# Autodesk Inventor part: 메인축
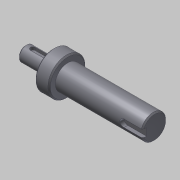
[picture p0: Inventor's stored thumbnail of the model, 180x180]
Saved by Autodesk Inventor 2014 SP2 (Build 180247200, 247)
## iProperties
Created: 2018-09
Part Number: 메인축
Document SubType Name: Modeling
Density: 7.86 g/cm^3
Material: 강철, 연강
Appearance: 강철
Mass: 251.949 g
Surface Area: 77.4412 cm^2
Volume: 32.0546 cm^3
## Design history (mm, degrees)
sketch "스케치1"
  geometry: L1 (34.997, -37.5)-(34.997, -77.5) reference; L2 (46.5, -38.401)-(46.5, -76.599) reference; L3 (12.497, -57.5)-(116.5, -57.5); L4 (12.497, -63.5)-(34.997, -63.5); L5 (34.997, -72.5)-(46.5, -72.5); L6 (46.5, -67.5)-(116.5, -67.5); L7 (116.5, -67.5)-(116.5, -57.5); L8 (12.497, -63.5)-(12.497, -57.5); 2 further points
  constraints: 12 end point, 5 point on line, 4 perpendicular, 1 midpoint, 1 parallel
  dimensions: "d0" = 20 diameter of L6 L3; "d1" = 30 diameter of L5 L3; "d2" = 22.5 distance of L4.start L4.end; "d3" = 70 distance of L6.start L6.end; "d5" = 12 diameter of L4 L3
revolve "회전1" sketch "스케치1" stored, may be unused: angle "d4" = 90 deg
chamfer "모따기1" distance "d6" = 1; stored, may be unused: second distance "d7" = 2, angle "d8" = 45 deg
node "작업 평면1"
sketch "스케치2"
  geometry: L1 (-11.25, -5)-(-11.25, 5) reference; L2 (-5.25, 2)-(4.75, 2); L3 (4.75, -2)-(-5.25, -2); A1 r 2 centre (4.75, 0) between (4.75, -2) and (4.75, 2); A2 r 2 centre (-5.25, 0) between (-5.25, 2) and (-5.25, -2); 2 further points
  constraints: 4 end point, 4 point on circle, 4 tangent, 2 centre point, 1 horizontal alignment, 1 midpoint, 1 parallel, 1 perpendicular
  dimensions: "d9" = 4 distance between parallel lines of L3 L2; "d10" = 14 dimension on A1 A2; "d11" = 4 distance edge to line of A2 L1
extrude "돌출1" cut sketch "스케치2" distance "d12" = 2.5; taper "d13" = 0 deg
node "작업 평면2"
sketch "스케치3"
  geometry: L1 (35, 9)-(35, -9) reference; L2 (35, 3)-(20, 3); L3 (20, -3)-(35, -3); A1 r 3 centre (20, 0) between (20, 3) and (20, -3); 2 further points
  constraints: 4 end point, 2 perpendicular, 2 point on circle, 2 point on line, 2 tangent, 1 centre point, 1 horizontal alignment, 1 midpoint
  dimensions: "d14" = 6 distance between parallel lines of L3 L2; "d15" = 18 dimension on A1 L1
extrude "돌출2" cut sketch "스케치3" distance "d16" = 3.5; taper "d17" = 0 deg
node "솔리드1"
node "참조1"
node "참조2"
